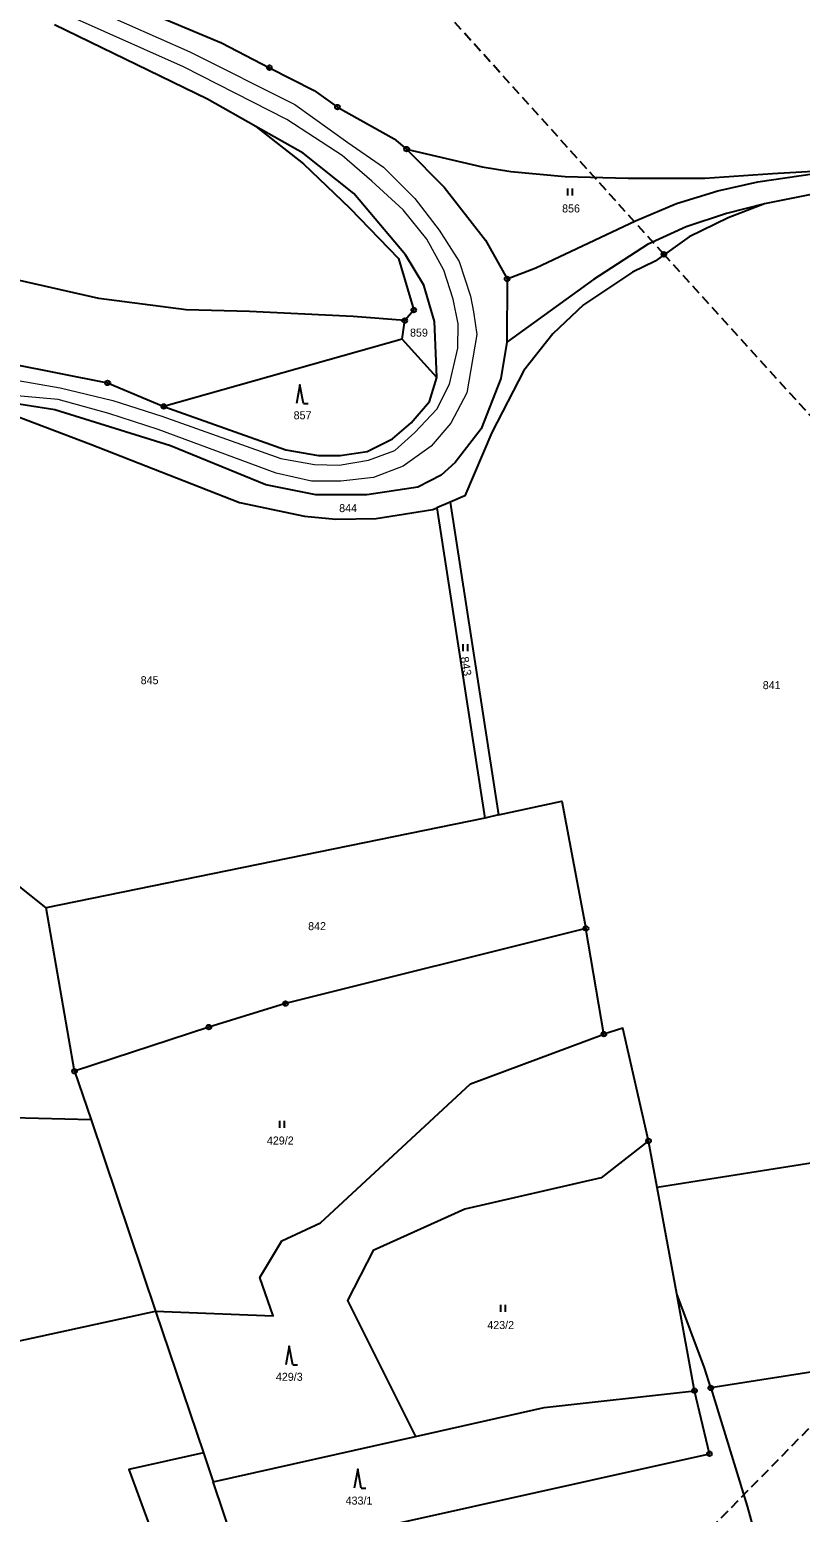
# Model space of a CAD drawing. Extents: x -754445 to -751443, y -1030748 to -1028224.
# Drawn here: x -753837.5 to -753673.8, y -1028877.9 to -1028563 of the extents above; entities that cross this region are included whole.
import ezdxf
from ezdxf.enums import TextEntityAlignment as Align

# ---------------------------------------------------------------- set-up
doc = ezdxf.new("R2010")
doc.units = 0
doc.header["$LTSCALE"] = 0.68
doc.linetypes.add('MEDIUM_DASHED', pattern=[4.5, 3, -1.5])
for name, color, linetype, lineweight in [('1', 7, 'Continuous', 25), ('3', 7, 'Continuous', 25), ('4', 7, 'Continuous', 13), ('6', 7, 'Continuous', 25), ('8', 7, 'Continuous', 25)]:
    doc.layers.add(name, color=color, linetype=linetype, lineweight=lineweight)
doc.layers.add('2', color=7, linetype='Continuous')

msp = doc.modelspace()

# ---------------------------------------------------------------- linework, layer by layer
at = {"layer": '1'}
for p, q in [((-753736.1, -1028615.95), (-753736.16, -1028629.35)), ((-753758.37, -1028628.73), (-753757.86, -1028624.79)), ((-753748.18, -1028663.33), (-753737.93, -1028729.8)), ((-753740.86, -1028730.45), (-753833.98, -1028749.49)), ((-753737.93, -1028729.8), (-753740.86, -1028730.45)), ((-753827.97, -1028784.21), (-753833.98, -1028749.49)), ((-753827.97, -1028784.21), (-753824.48, -1028794.54)), ((-753824.48, -1028794.54), (-753810.76, -1028835.18)), ((-753602.43, -1028792.77), (-753704.24, -1028808.88)), ((-753810.76, -1028835.18), (-753800.61, -1028865.27)), ((-753581.69, -1028833.89), (-753692.86, -1028851.48)), ((-753793.04, -1028887.7), (-753798.53, -1028871.44))]:
    msp.add_line(p, q, dxfattribs=at)
for points in [[(-753757.86, -1028624.79), (-753768.78, -1028623.93), (-753790.82, -1028622.87), (-753804.27, -1028622.52), (-753822.85, -1028620.1), (-753848.19, -1028614.39), (-753858.06, -1028610.35), (-753864.41, -1028606.2), (-753874.22, -1028598.34), (-753897.57, -1028582.87), (-753918.75, -1028564.3), (-753931.84, -1028557.78), (-753946.83, -1028549.73), (-753947.94, -1028547.26), (-753941.11, -1028626.59)], [(-753818.43, -1028556.78), (-753796.76, -1028565.81), (-753786.6, -1028571.09), (-753777.09, -1028575.95), (-753772.14, -1028579.47), (-753760.07, -1028586.18), (-753757.44, -1028588.37)], [(-753789.48, -1028583.58), (-753799.74, -1028577.76), (-753832.22, -1028562.02)], [(-753789.48, -1028583.58), (-753779.33, -1028591.53), (-753769.54, -1028600.92), (-753759.2, -1028611.61), (-753755.94, -1028622.57), (-753757.86, -1028624.79)], [(-753751.03, -1028636.87), (-753751.42, -1028628.34), (-753751.54, -1028625.01), (-753753.77, -1028617.26), (-753757.72, -1028610.82), (-753768.63, -1028597.83), (-753779.42, -1028589.28), (-753789.48, -1028583.58)], [(-753757.44, -1028588.37), (-753741.39, -1028592.15), (-753735.32, -1028593.12), (-753723.76, -1028594.17), (-753710.4, -1028594.56), (-753694.11, -1028594.53), (-753679.73, -1028593.58), (-753664.93, -1028592.7)], [(-753757.44, -1028588.37), (-753749.48, -1028596.44), (-753740.67, -1028607.71), (-753736.1, -1028615.95)], [(-753736.1, -1028615.95), (-753729.98, -1028613.58), (-753708.8, -1028603.59), (-753700.16, -1028599.93), (-753691.37, -1028597.23), (-753682.82, -1028595.32), (-753664.93, -1028592.7)], [(-753602.43, -1028792.77), (-753603.82, -1028789.84), (-753607.43, -1028779.89), (-753609.98, -1028769.97), (-753611.95, -1028759.3), (-753613.71, -1028745.3), (-753615.11, -1028722.54), (-753619.57, -1028621.02), (-753620, -1028612.08), (-753620.63, -1028606.28), (-753621.75, -1028602.34), (-753623.45, -1028600.13), (-753625.89, -1028597.61), (-753628.2, -1028596.18), (-753630.98, -1028595.31), (-753633.7, -1028594.68), (-753638.29, -1028594.26), (-753646.46, -1028594.85), (-753667.98, -1028597.29), (-753681.46, -1028600)], [(-753681.46, -1028600), (-753689.14, -1028602.99), (-753697.46, -1028607.03), (-753704.65, -1028612.16), (-753709.45, -1028614.52), (-753719.87, -1028621.45), (-753726.41, -1028627.62), (-753732.53, -1028635.41), (-753739.38, -1028648.6), (-753745.05, -1028662), (-753748.18, -1028663.33)], [(-753681.46, -1028600), (-753689.52, -1028602.07), (-753698.1, -1028604.92), (-753706.27, -1028608.63), (-753717.73, -1028616.04), (-753736.16, -1028629.35)], [(-753941.11, -1028626.59), (-753932.21, -1028625.73), (-753922.69, -1028625.7), (-753841.68, -1028633.91), (-753820.95, -1028638.03), (-753809.01, -1028643.04)], [(-753736.16, -1028629.35), (-753737.44, -1028637.12), (-753741.64, -1028647.79), (-753747.15, -1028654.93), (-753750.09, -1028657.64), (-753755.09, -1028660.2), (-753765.89, -1028661.82), (-753776.73, -1028661.79), (-753787.35, -1028659.65), (-753807.6, -1028651.42), (-753832.14, -1028643.73), (-753844.85, -1028641.75), (-753844.08, -1028643.7)], [(-753751.03, -1028636.87), (-753758.37, -1028628.73), (-753809.01, -1028643.04)], [(-753809.01, -1028643.04), (-753783.13, -1028652.23), (-753776.14, -1028653.48), (-753771.53, -1028653.48), (-753765.85, -1028652.6), (-753760.48, -1028649.92), (-753756.48, -1028646.53), (-753752.56, -1028642.01), (-753751.03, -1028636.87)], [(-753844.08, -1028643.7), (-753824.56, -1028651.03), (-753792.93, -1028663.41), (-753779.15, -1028666.35), (-753772.49, -1028666.98), (-753763.92, -1028666.84), (-753751.85, -1028664.9), (-753751.02, -1028664.55)], [(-753748.18, -1028663.33), (-753751.02, -1028664.55), (-753740.86, -1028730.45)], [(-753824.48, -1028794.54), (-753852.52, -1028793.8), (-753853.23, -1028795.76), (-753860.06, -1028796.74), (-753867.9, -1028781.61), (-753877.61, -1028767.45), (-753888.16, -1028745.42), (-753893.58, -1028728.83), (-753901.54, -1028712.8), (-753902.32, -1028707.36), (-753900.18, -1028697.4), (-753876.47, -1028715.68)], [(-753833.98, -1028749.49), (-753873.33, -1028718.18), (-753876.47, -1028715.68)], [(-753737.93, -1028729.8), (-753724.51, -1028726.83), (-753719.35, -1028753.9)], [(-753719.35, -1028753.9), (-753783.19, -1028769.86), (-753799.43, -1028774.85), (-753827.97, -1028784.21)], [(-753810.76, -1028835.18), (-753785.79, -1028836.13), (-753788.64, -1028828.01), (-753783.96, -1028820.21), (-753775.76, -1028816.4), (-753743.87, -1028786.91), (-753715.56, -1028776.34), (-753719.35, -1028753.9)], [(-753706.06, -1028799.01), (-753711.54, -1028775.07), (-753715.56, -1028776.34)], [(-753706.06, -1028799.01), (-753716.15, -1028806.83), (-753745.06, -1028813.53), (-753764.56, -1028822.27), (-753770.02, -1028832.88), (-753755.54, -1028861.76)], [(-753696.28, -1028852.07), (-753700.08, -1028831.47), (-753704.24, -1028808.88), (-753706.06, -1028799.01)], [(-753692.86, -1028851.48), (-753694.19, -1028847.2), (-753700.08, -1028831.47)], [(-753884.58, -1028837.35), (-753873.85, -1028848.94), (-753810.76, -1028835.18)], [(-753692.86, -1028851.48), (-753685.1, -1028876.55), (-753681.87, -1028888.38)], [(-753793.04, -1028887.7), (-753693.13, -1028865.44), (-753696.28, -1028852.07)], [(-753755.54, -1028861.76), (-753728.24, -1028855.61), (-753696.28, -1028852.07)], [(-753800.61, -1028865.27), (-753798.53, -1028871.44), (-753755.54, -1028861.76)], [(-753800.61, -1028865.27), (-753816.47, -1028868.81), (-753796.73, -1028922.46), (-753773.56, -1028944.25)]]:
    msp.add_lwpolyline(points, dxfattribs=at)
at = {"layer": '3'}
for p, q in [((-753723.211, -1028598.22), (-753723.211, -1028596.72)), ((-753722.21, -1028598.22), (-753722.21, -1028596.72)), ((-753779.35, -1028642.42), (-753778.354, -1028642.42)), ((-753745.431, -1028695.04), (-753745.431, -1028693.54)), ((-753744.43, -1028695.04), (-753744.43, -1028693.54)), ((-753784.411, -1028796.27), (-753784.411, -1028794.77)), ((-753783.41, -1028796.27), (-753783.41, -1028794.77)), ((-753737.431, -1028835.34), (-753737.431, -1028833.84)), ((-753736.43, -1028835.34), (-753736.43, -1028833.84)), ((-753781.62, -1028846.6), (-753780.624, -1028846.6)), ((-753767.09, -1028872.74), (-753766.094, -1028872.74))]:
    msp.add_line(p, q, dxfattribs=at)
for points in [[(-753779.35, -1028642.42), (-753780.1, -1028638.42), (-753780.85, -1028642.42)], [(-753781.62, -1028846.6), (-753782.37, -1028842.6), (-753783.12, -1028846.6)], [(-753767.09, -1028872.74), (-753767.84, -1028868.74), (-753768.59, -1028872.74)]]:
    msp.add_lwpolyline(points, dxfattribs=at)
at = {"layer": '4'}
for points in [[(-753837.16, -1028552.8), (-753803.48, -1028567.75), (-753781.2, -1028578.93), (-753769.95, -1028586.99), (-753762.38, -1028592.24), (-753755.73, -1028598.86), (-753750.55, -1028605.62), (-753746.27, -1028612.26), (-753743.87, -1028619.63), (-753743.21, -1028622.95), (-753742.56, -1028627.74), (-753744.68, -1028640.13), (-753748.03, -1028646.56), (-753752.21, -1028651.45), (-753758.2, -1028655.69), (-753764.48, -1028658.13), (-753771.45, -1028658.87), (-753777.64, -1028658.91), (-753785.15, -1028657.24), (-753810.22, -1028647.96), (-753820.73, -1028644.56), (-753831.43, -1028641.58), (-753845.05, -1028640.37)], [(-753841.61, -1028637.23), (-753831.01, -1028639.06), (-753819.87, -1028641.8), (-753809.46, -1028645.09), (-753784.17, -1028654.12), (-753777.04, -1028655.33), (-753771.77, -1028655.52), (-753765.53, -1028654.43), (-753759.94, -1028652.42), (-753755.73, -1028648.6), (-753751.06, -1028643.62), (-753748.37, -1028638.32), (-753746.59, -1028630.65), (-753746.49, -1028625.52), (-753747.57, -1028620.25), (-753749.53, -1028614.06), (-753753.14, -1028607.49), (-753758.19, -1028601.31), (-753764.81, -1028595.16), (-753771.15, -1028589.74), (-753782.88, -1028582.09), (-753804.84, -1028570.93), (-753838.56, -1028555.86)]]:
    msp.add_lwpolyline(points, dxfattribs=at)
at = {"layer": '6', "linetype": 'MEDIUM_DASHED'}
for points in [[(-753499.83, -1028865.29), (-753527.61, -1028823.3), (-753570.95, -1028756.74), (-753608.62, -1028714.93), (-753648.01, -1028671.11), (-753702.8, -1028610.73), (-753758.07, -1028549.45), (-753816.14, -1028485.34), (-753875.16, -1028419.8), (-753934.32, -1028354.21)], [(-753310.54, -1028491.05), (-753376.98, -1028558.72), (-753440.66, -1028623.53), (-753506.62, -1028691.15), (-753570.95, -1028756.74), (-753615.01, -1028801.84), (-753659.25, -1028847.07), (-753726.53, -1028915.66), (-753765.82, -1028955.94), (-753892, -1029023.9)]]:
    msp.add_lwpolyline(points, dxfattribs=at)
at = {"layer": '6'}
for radius in [0.5, 0.4, 0.3, 0.2, 0.1]:
    msp.add_circle((-753702.8034, -1028610.7299), radius, dxfattribs=at)
at = {"layer": '8'}
for centre, radius in [((-753786.6, -1028571.0899), 0.5), ((-753786.6, -1028571.0899), 0.0303), ((-753772.14, -1028579.4699), 0.5), ((-753772.14, -1028579.4699), 0.0303), ((-753757.44, -1028588.3699), 0.5), ((-753757.44, -1028588.3699), 0.0303), ((-753736.1, -1028615.9499), 0.5), ((-753736.1, -1028615.9499), 0.0303), ((-753755.94, -1028622.5699), 0.5), ((-753757.86, -1028624.7899), 0.5), ((-753757.86, -1028624.7899), 0.0303), ((-753755.94, -1028622.5699), 0.0303), ((-753820.95, -1028638.0299), 0.5), ((-753820.95, -1028638.0299), 0.0303), ((-753809.01, -1028643.0399), 0.5), ((-753809.01, -1028643.0399), 0.0303), ((-753719.35, -1028753.8999), 0.5), ((-753719.35, -1028753.8999), 0.0303), ((-753783.19, -1028769.8599), 0.5), ((-753783.19, -1028769.8599), 0.0303), ((-753799.43, -1028774.8499), 0.5), ((-753799.43, -1028774.8499), 0.0303), ((-753715.56, -1028776.3399), 0.5), ((-753715.56, -1028776.3399), 0.0303), ((-753827.97, -1028784.2099), 0.5), ((-753827.97, -1028784.2099), 0.0303), ((-753706.06, -1028799.0099), 0.5), ((-753706.06, -1028799.0099), 0.0303), ((-753696.28, -1028852.0699), 0.5), ((-753692.86, -1028851.4799), 0.5), ((-753692.86, -1028851.4799), 0.0303), ((-753696.28, -1028852.0699), 0.0303), ((-753693.13, -1028865.4399), 0.5), ((-753693.13, -1028865.4399), 0.0303)]:
    msp.add_circle(centre, radius, dxfattribs=at)

# ---------------------------------------------------------------- texts
at = {"layer": '2'}
for s, p in [('856', (-753722.529, -1028601.836)), ('859', (-753754.829, -1028628.206)), ('857', (-753779.549, -1028645.756)), ('844', (-753769.879, -1028665.476)), ('845', (-753812.039, -1028702.026)), ('841', (-753679.909, -1028703.076)), ('842', (-753776.479, -1028754.256)), ('429/2', (-753784.28, -1028799.78)), ('423/2', (-753737.47, -1028838.97)), ('429/3', (-753782.37, -1028849.96)), ('433/1', (-753767.56, -1028876.25))]:
    msp.add_text(s, height=1.7, dxfattribs=at).set_placement(p, align=Align.CENTER)
at = {"layer": '2', "width": 1.1}
msp.add_text('843', height=1.7, rotation=280, dxfattribs=at).set_placement((-753745.6577, -1028698.3544), align=Align.CENTER)

doc.saveas('drawing.dxf')
